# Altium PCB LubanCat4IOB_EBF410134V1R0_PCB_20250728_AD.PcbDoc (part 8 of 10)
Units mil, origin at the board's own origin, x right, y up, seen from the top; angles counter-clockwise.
Board outline 5236.21 x 4055.11 mil, 6 copper layers (TOP, GND02, ART03, PWR04, GND05, BOTTOM), stack 47.2 mil thick; 614 components, 490 nets, 2311 pads, 1916 vias.
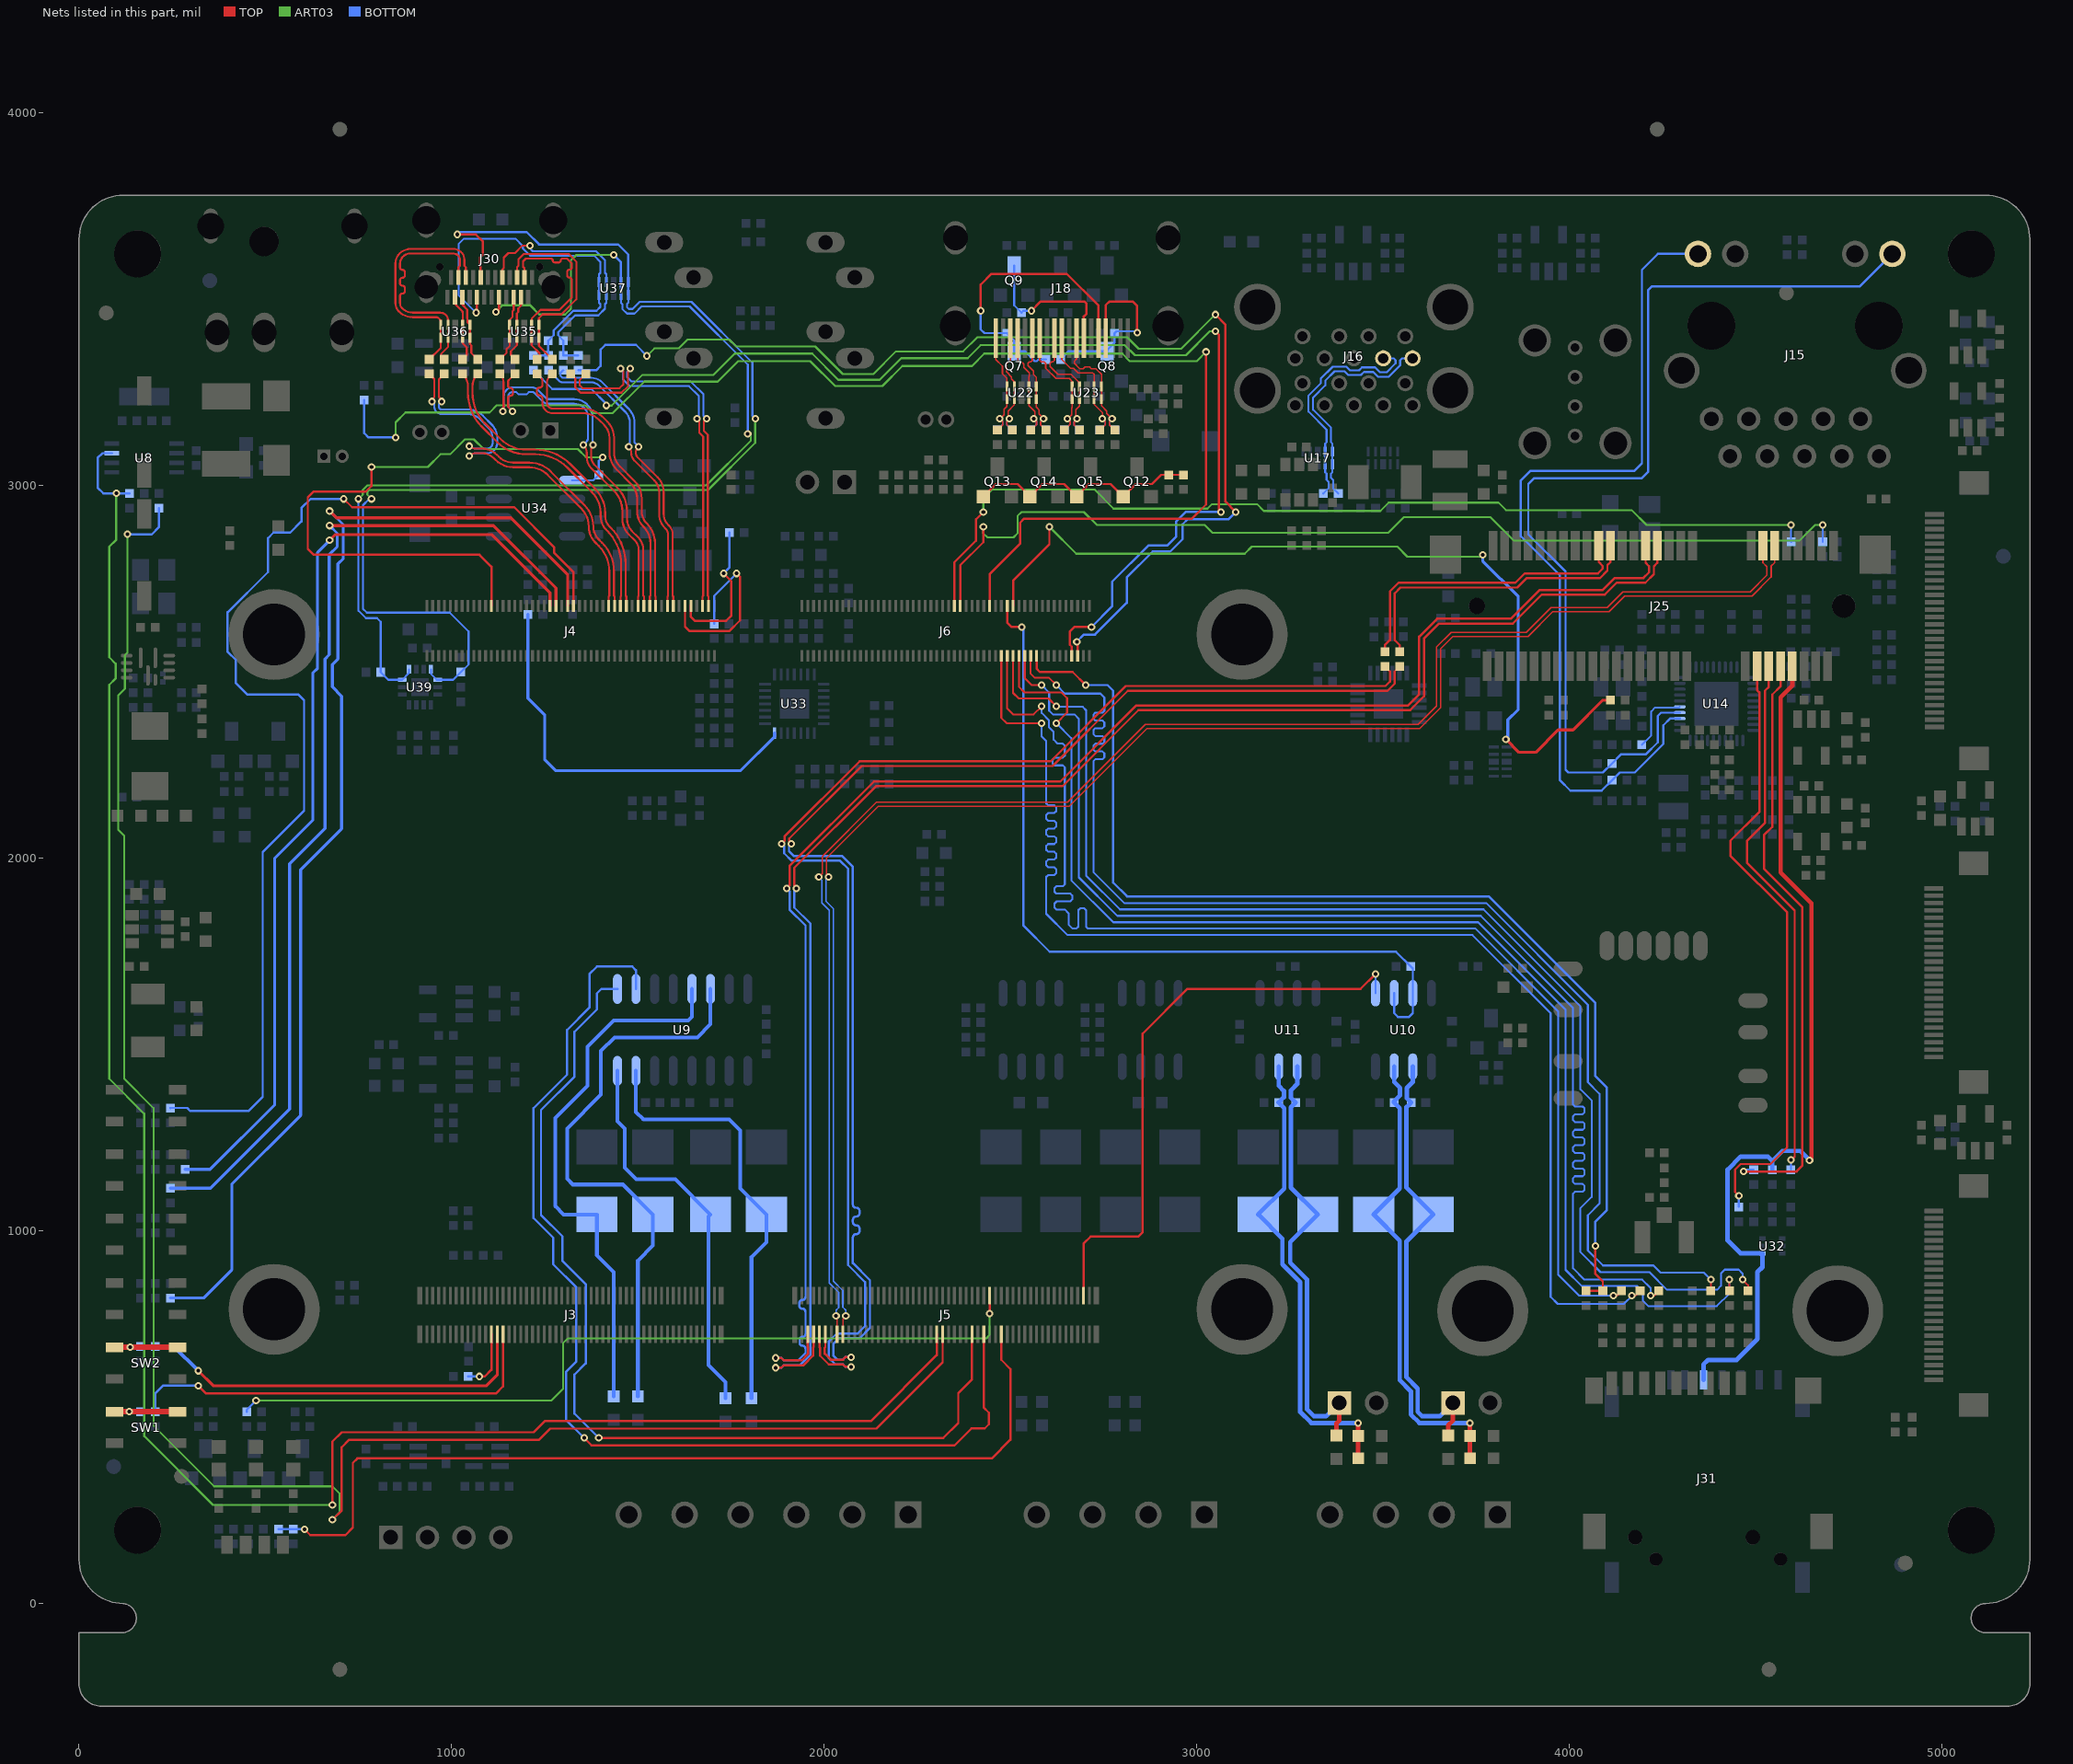
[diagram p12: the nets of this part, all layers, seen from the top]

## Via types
v1: diameter 20, hole 10, TOP to BOTTOM, 1912 vias
v2: diameter 40/50/50/50/50/40 (per signal layer), hole 0, TOP to BOTTOM, 4 vias

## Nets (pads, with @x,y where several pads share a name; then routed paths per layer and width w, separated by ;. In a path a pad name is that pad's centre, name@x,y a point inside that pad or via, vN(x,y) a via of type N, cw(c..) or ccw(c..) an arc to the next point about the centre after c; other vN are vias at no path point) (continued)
OUT2_R: R204.1 U33.14 | length 1085.1
  BOTTOM w8: R204.1@1205,2654.69 1205,2429.37 1250,2384.37 1250,2264.01 1278.64,2235.37 1776,2235.37 1866.85,2326.22 U33.14@1866.85,2335.63
PCIE20_0_CLKN: J5.16 J25.11 | length 4336.7
  TOP w4.2: v1(2011.35,1949.72) 2006.2,1954.87 2006.2,2000.57 2145,2139.37 2657.64,2139.37 2866.24,2347.97 3598.6,2347.97 3655,2404.37 3655,2562.53 3687.64,2595.17 3889,2595.17 3955.6,2661.77 4106.44,2661.77 4148.44,2703.77 4490.4,2703.77 4541.78,2755.15 4541.78,2783.79 4551.32,2793.34 J25.11@4551.32,2838.58 ; J5.16@2050.39,722.26 2050.39,763.87 v1(2058.08,771.56)
  BOTTOM w4.2: v1(2011.35,1949.72) 2010.65,1949.72 2005.1,1944.17 2005.1,1884.34 2024.6,1864.84 2024.6,865.05 2050.07,839.58 2050.07,795.19 2058.08,787.19 v1(2058.08,771.56)
PCIE20_0_CLKP: J5.14 J25.13 | length 4337
  TOP w4.2: v1(1985.35,1949.72) 1995,1959.37 1995,2005.21 2140.36,2150.57 2653,2150.57 2861.6,2359.17 3593.96,2359.17 3643.8,2409.01 3643.8,2567.17 3683,2606.37 3884.36,2606.37 3950.96,2672.97 4101.8,2672.97 4143.8,2714.97 4485.76,2714.97 4530.58,2759.79 4530.58,2782.59 4519.83,2793.34 J25.13@4519.83,2838.58 ; v1(2032.08,771.56) 2034.64,769 J5.14@2034.64,722.26
  BOTTOM w4.2: v1(1985.35,1949.72) 1993.9,1941.17 1993.9,1879.7 2013.4,1860.2 2013.4,860.41 2038.87,834.94 2038.87,793.98 2032.08,787.19 v1(2032.08,771.56)
PCIE20_0_RXN: J5.6 J25.23 | length 4413.3
  TOP w5.9: v1(1869.39,632.82) 1885.17,632.82 1891.72,639.37 1944.77,639.37 1970.23,664.83 1970.23,686.51 1971.65,687.94 J5.6@1971.65,722.26 ; v1(1925,1919.37) 1920,1924.37 1920,1974.37 2139,2193.37 2639.6,2193.37 2843.65,2397.42 3573.05,2397.42 3610,2434.37 3610,2589.37 3650.6,2629.97 3848.6,2629.97 3926,2707.37 4095.37,2707.37 4127.37,2739.37 4204.2,2739.37 4227.06,2762.23 4227.06,2783.69 4236.36,2792.99 J25.23@4236.36,2838.58
  BOTTOM w5.9: v1(1869.39,632.82) 1885.17,632.82 1891.72,639.37 1935,639.37 1962.85,667.22 1962.85,1825.05 1920,1867.9 1920,1914.37 v1(1925,1919.37)
PCIE20_0_RXP: J5.4 J25.25 | length 4410.4
  TOP w5.9: v1(1869.39,658.82) 1885.17,658.82 1891.72,652.27 1939.43,652.27 1957.33,670.17 1957.33,686.51 1955.9,687.94 J5.4@1955.9,722.26 ; v1(1899,1919.37) 1907.1,1927.47 1907.1,1979.71 2133.66,2206.27 2634.26,2206.27 2838.31,2410.32 3567.71,2410.32 3597.1,2439.71 3597.1,2594.71 3645.26,2642.87 3843.26,2642.87 3920.66,2720.27 4090.03,2720.27 4122.03,2752.27 4198.86,2752.27 4214.16,2767.58 4214.16,2783.69 4204.87,2792.99 J25.25@4204.87,2838.58
  BOTTOM w5.9: v1(1869.39,658.82) 1885.17,658.82 1891.72,652.27 1929.65,652.27 1949.95,672.57 1949.95,683.8 ccw(c1941.97,683.8) 1941.97,691.77 cw(c1941.97,699.75) 1934,699.75 1934,707.4 cw(c1941.97,707.4) 1941.97,715.37 ccw(c1941.97,723.35) 1949.95,723.35 1949.95,782.58 ccw(c1941.58,782.58) 1941.58,790.95 cw(c1941.58,799.33) 1933.2,799.33 1933.2,806.18 cw(c1941.58,806.18) 1941.58,814.55 ccw(c1941.58,822.93) 1949.95,822.93 1949.95,1819.7 1907.1,1862.56 1907.1,1911.27 v1(1899,1919.37)
PCIE20_0_TXN: C156.1 J5.10 | length 3710.4
  TOP w5.9: v1(1912.24,2038.68) 1906.41,2044.51 1906.41,2052.86 2100.92,2247.37 2613.24,2247.37 2815.24,2449.37 3512.09,2449.37 3531.45,2468.73 3531.45,2501.14 C156.1@3545,2514.69 ; J5.10@2003.15,722.26 2003.15,687.94 2001.72,686.51 2001.72,670.27 2017.62,654.37 2050.33,654.37 2056.88,660.92 v1(2072.66,660.92)
  BOTTOM w5.9: v1(1912.24,2038.68) 1905.69,2032.13 1905.69,2018.68 1918,2006.37 2048,2006.37 2077,1977.37 2077,1071.03 ccw(c2086,1071.03) 2086,1062.03 cw(c2086,1053.03) 2095,1053.03 2095,1047.43 cw(c2086,1047.43) 2086,1038.43 ccw(c2086,1029.43) 2077,1029.43 2077,1023.83 ccw(c2086,1023.83) 2086,1014.83 cw(c2086,1005.83) 2095,1005.83 2095,1000.23 cw(c2086,1000.23) 2086,991.23 ccw(c2086,982.23) 2077,982.23 2077,913.61 2123,867.61 2123,739.37 2095.1,711.47 2038.8,711.47 2025,697.67 2025,664.8 2035.43,654.37 2050.33,654.37 2056.88,660.92 v1(2072.66,660.92)
PCIE20_0_TXP: C157.1 J5.8 | length 3712.6
  TOP w5.9: v1(1886.24,2038.68) 1893.29,2045.73 1893.29,2046.53 1893.51,2046.76 1893.51,2058.2 2095.58,2260.27 2607.9,2260.27 2809.9,2462.27 3506.75,2462.27 3518.55,2474.07 3518.55,2501.14 C157.1@3505,2514.69 ; J5.8@1987.4,722.26 1987.4,687.94 1988.82,686.51 1988.82,664.93 2012.28,641.47 2050.33,641.47 2056.88,634.92 v1(2072.66,634.92)
  BOTTOM w5.9: v1(1886.24,2038.68) 1892.79,2032.13 1892.79,2013.34 1912.66,1993.47 2042.66,1993.47 2064.1,1972.03 2064.1,908.27 2110.1,862.27 2110.1,744.71 2089.76,724.37 2033.46,724.37 2012.1,703.01 2012.1,659.46 2030.09,641.47 2050.33,641.47 2056.88,634.92 v1(2072.66,634.92)
PCIE20X1_2_CLKREQN_M0: J6.54 R179.1 | length 2611.2
  TOP w6: J6.54@2349.6,2677.37 2349.6,2794.35 2407.62,2852.37 2407.62,2909.68 v1(2427.31,2929.37)
  ART03 w5.5: v1(2427.31,2929.37) 2427.31,2966.68 2450,2989.37 2726,2989.37 2777,2938.37 3029,2938.37 3041,2950.37 3162,2950.37 3180,2932.37 3493,2932.37 3515,2954.37 3810,2954.37 3830,2934.37 4167.2,2934.37 4207.2,2894.37 v1(4595,2894.37)
  BOTTOM w6: v1(4595,2894.37) 4595,2849.69 R179.1@4595.32,2849.37
PCIE20X1_2_PERSTN_M0: J6.74 R181.2 | length 2367.2
  TOP w6: J6.74@2507.08,2677.37 2507.08,2745.25 2604.47,2842.64 v1(2604.47,2889.37)
  TOP w8: v1(3830,2319.37) 3865,2284.37 3910,2284.37 3970,2344.37 4010,2344.37 4090,2424.37 R181.2@4110.32,2424.37
  ART03 w5.5: v1(2604.47,2889.37) 2676.47,2817.37 3129,2817.37 3148,2836.37 3538.4,2836.37 3565.2,2809.57 3762.81,2809.57 v1(3767.61,2814.37)
  BOTTOM w8: v1(3767.61,2814.37) 3767.61,2797.99 3863,2702.6 3863,2399.33 3835,2371.33 3835,2324.37 v1(3830,2319.37)
PCIE20X1_2_WAKEN_M0: J6.56 R178.1 | length 2697
  TOP w6: J6.56@2365.35,2677.37 2365.35,2786.41 2427.31,2848.37 v1(2427.31,2889.37)
  ART03 w5.5: v1(2427.31,2889.37) 2427.31,2872 2438.31,2861 2508,2861 2519,2872 2519,2918.37 2530,2929.37 2697,2929.37 2732,2894.37 3021,2894.37 3042,2873.37 3514,2873.37 3556,2915.37 3788,2915.37 3850.8,2852.57 4618.2,2852.57 4660,2894.37 v1(4680.32,2894.37)
  BOTTOM w6: R178.1@4680.32,2849.37 v1(4680.32,2894.37)
PE_TXN: C156.2 J25.31 | length 828.7
  TOP w5.9: C156.2@3545,2554.05 3545,2572.07 3531.45,2585.62 3531.45,2710.82 3547.1,2726.47 3860.34,2726.47 3885.34,2751.47 4082.1,2751.47 4102.52,2771.89 4102.52,2786.89 4110.38,2794.75 J25.31@4110.38,2838.58
PE_TXP: C157.2 J25.33 | length 829.9
  TOP w5.9: C157.2@3505,2554.05 3505,2572.07 3518.55,2585.62 3518.55,2716.16 3541.76,2739.37 3855,2739.37 3880,2764.37 4076.76,2764.37 4089.62,2777.23 4089.62,2784.75 4078.88,2795.49 J25.33@4078.88,2838.58
PHY1_CLKOUT125: R97.2 U14.35 | length 182
  BOTTOM w5.2: R97.2@4194.68,2304.37 4220,2329.69 4220,2394.16 4230.48,2404.64 4294.71,2404.64 U14.35@4296.57,2406.5
PHY1_LED1: J15.14 R103.1 U14.33 | length 2322.3
  BOTTOM w6: U14.33@4296.57,2375 4270.63,2375 4252.5,2356.87 4252.5,2306.87 4175.8,2230.17 4135.48,2230.17 R103.1@4114.68,2209.37 4086.68,2181.37 4003,2181.37 3975,2209.37 3975,2759.37 3870,2864.37 3870,3014.37 3895,3039.37 4174,3039.37 4195,3060.37 4195,3579.37 4237.68,3622.05 J15.14@4345.46,3622.05
PHY1_LED2: J15.11 R102.1 U14.34 | length 2744.8
  BOTTOM w6: U14.34@4296.57,2390.75 4246.38,2390.75 4237.6,2381.97 4237.6,2310.96 4206.01,2279.37 4139.68,2279.37 R102.1@4114.68,2254.37 4090.48,2230.17 3997.33,2230.17 3990,2237.5 3990,2769.37 3890,2869.37 3890,3004.37 3905,3019.37 4194,3019.37 4212,3037.37 4212,3525.37 4221,3534.37 4779.44,3534.37 J15.11@4867.12,3622.05
PWM7_IR_M0: C46.1 J5.70 R45.1 | length 2472.5
  TOP w6: v1(605,199.05) 620.68,183.37 715,183.37 735,203.37 735,377.37 747,389.37 2450,389.37 2500,439.37 2500,629.37 2475.59,653.78 J5.70@2475.59,722.26
  BOTTOM w6: R45.1@535,199.05 C46.1@575,199.05 v1(605,199.05)
PWRON_EN: J3.24 R238.2 | length 164.6
  TOP w6: v1(1075,609.37) 1089,609.37 1106.78,627.15 J3.24@1106.78,722.26
  BOTTOM w6: R238.2@1044.68,609.37 v1(1075,609.37)
PWRON_KEY: C39.1 J3.28 SW1.3 SW1.4 Z1.2 | length 1387.8
  TOP w6: v1(320,584.37) 341,563.37 1119,563.37 1138.28,582.65 J3.28@1138.28,722.26
  TOP w15: SW1.3@95.35,514.76 v1(135,514.76) SW1.4@264.65,514.76
  BOTTOM w6: v1(135,514.76) 135.71,514.05 Z1.2@165,514.05 C39.1@205,514.05 205,564.37 225,584.37 v1(320,584.37)
RESET_KEY: C41.1 J3.26 SW2.3 SW2.4 Z2.2 | length 1320
  TOP w8: v1(320,624.37) 360,584.37 1094,584.37 1122.53,612.9 J3.26@1122.53,722.26
  TOP w15: SW2.3@95.35,687.48 v1(137.52,687.48) SW2.4@264.65,687.48
  BOTTOM w10: v1(137.52,687.48) 139.72,689.68 Z2.2@165,689.68 C41.1@205,689.68 254.69,689.68 v1(320,624.37)
RS485_1_A: D20.2 J11.1 R62.2 R67.1 U10.6 | length 1222.4
  TOP w12: R67.1@3675,450.87 3675,478.02 3687.67,490.69 J11.1@3687.67,538.19
  BOTTOM w12: U10.6@3580,1440.94 3580,1399.37 3563.65,1383.02 3563.65,1356.04 R62.2@3575.32,1344.37 3563,1332.05 3563,1115.82 D20.2@3635,1043.82 3563,971.82 3563,606.83 3593,576.83 3593,514.37 3605,502.37 3651.85,502.37 J11.1@3687.67,538.19
RS485_1_B: D18.2 R63.1 R64.1 R66.1 U10.7 | length 1286.7
  TOP w12: R66.1@3733.5,389.37 R63.1@3733.5,449.37 v1(3733.5,484.37)
  BOTTOM w12: U10.7@3530,1440.94 3530,1399.37 3545.65,1383.72 3545.65,1363.54 3529.68,1347.58 R64.1@3529.68,1344.37 3545,1329.05 3545,1113.82 D18.2@3475,1043.82 3545,973.82 3545,599.37 3575,569.37 3575,506.91 3597.54,484.37 v1(3733.5,484.37)
RS485_2_A: D22.2 J13.1 R69.1 R70.2 U11.6 | length 1216
  TOP w12: R69.1@3375,450.87 3375,483.02 3382.67,490.69 J13.1@3382.67,538.19
  BOTTOM w12: U11.6@3270,1440.94 3270,1394.37 3253,1377.37 3253,1356.69 R70.2@3265.32,1344.37 3252.88,1331.93 3252.88,1115.94 D22.2@3325,1043.82 3251,969.82 3251,914.57 3295.6,869.97 3295.6,521.57 3314.8,502.37 3346.85,502.37 J13.1@3382.67,538.19
RS485_2_B: D21.2 R68.1 R71.1 R72.1 U11.7 | length 1283.7
  TOP w12: R68.1@3433.5,389.37 R71.1@3433.5,449.37 v1(3433.5,484.37)
  BOTTOM w12: U11.7@3220,1440.94 3220,1389.37 3233.85,1375.52 3233.85,1358.54 R72.1@3219.68,1344.37 3234.88,1329.17 3234.88,1113.7 D21.2@3165,1043.82 3165.32,1043.82 3230,979.1 3230,910.11 3277.6,862.51 3277.6,514.11 3307.34,484.37 v1(3433.5,484.37)
RTC_32K_IN: J5.50 R48.2 | length 5227.3
  TOP w6: v1(680,224.37) 705,249.37 705,419.37 725,439.37 1235,439.37 1265,469.37 2140,469.37 2318.11,647.48 J5.50@2318.11,722.26
  ART03 w5.5: v1(130,2869.37) 130,2552 123,2545 123,2455.09 105,2437.09 105,2076.37 121,2060.37 121,1408.37 200,1329.37 200,477 362.63,314.37 680,314.37 700,294.37 700,244.37 v1(680,224.37)
  BOTTOM w6: v1(130,2869.37) 195,2869.37 215,2889.37 R48.2@215,2939.69
RTC_INT: J5.48 R46.2 U8.3 | length 5331.7
  TOP w6: v1(680,264.37) 680,434.37 705,459.37 1220,459.37 1250,489.37 2125,489.37 2302.36,666.73 J5.48@2302.36,722.26
  ART03 w6: v1(100,2979.37) 100,2855.37 81,2836.37 81,2539.37 98,2522.37 98,2482.37 81,2465.37 81,1408.37 175,1314.37 175,449.37 360,264.37 v1(680,264.37)
  BOTTOM w6: U8.3@88.39,3087.16 62.8,3087.16 50,3074.37 50,2994.37 65,2979.37 v1(100,2979.37) 100.32,2979.05 R46.2@135,2979.05
RXD1_232: D8.2 R51.1 U9.13 | length 1480
  BOTTOM w10: R51.1@1435,555.87 1435,889.37 1390,934.37 D8.2@1390,1043.82 1300.55,1043.82 1278,1066.37 1278,1302.37 1365,1389.37 1365,1494.37 1435,1564.37 1635,1564.37 1645.2,1574.57 U9.13@1645.2,1649.17
RXD2_232: D7.2 R49.1 U9.8 | length 1064.3
  BOTTOM w10: U9.8@1445.2,1429.57 1445.2,1294.17 1465,1274.37 1465,1169.37 1496,1138.37 1600.45,1138.37 D7.2@1695,1043.82 1689.75,1038.57 1689.75,639.62 1735,594.37 R49.1@1735,550.87
SARADC_BOOT: J4.52 R239.2 | length 3088.1
  TOP w6: v1(710.63,2964.37) 733,2942 1168,2942 1275,2835 1275,2820 1327.25,2767.75 J4.52@1327.25,2677.37
  BOTTOM w6: R239.2@245,1329.68 245.32,1330 290,1330 298.49,1321.51 454.51,1321.51 493,1360 493,2017 604,2128 604,2424 589,2439 452,2439 421,2470 421,2532 399,2554 399,2660 507,2768 507,2859 522,2874 567,2874 597,2904 597,2940 621.37,2964.37 v1(710.63,2964.37)
SARADC_IN1/REC: J4.50 R28.2 | length 3186.8
  TOP w8: v1(672.63,2932.11) 691,2913.74 1159.63,2913.74 1311.5,2761.87 J4.50@1311.5,2677.37
  BOTTOM w8: R28.2@245,819.69 334.69,819.69 410,895 410,1125 595,1310 595,1969.37 705,2079.37 705,2435 680,2460 680,2520 695,2535 695,2790 709,2804 709,2895.74 v1(672.63,2932.11)
SARADC_IN4: J4.46 R31.2 | length 2759.8
  TOP w8: v1(672.63,2892.74) 1112.63,2892.74 1280.01,2725.36 J4.46@1280.01,2677.37
  BOTTOM w8: R31.2@245,1114.68 352.68,1114.68 565,1327 565,1985 660,2080 660,2535 671.31,2546.31 671.31,2814.68 693,2836.37 693,2872.37 v1(672.63,2892.74)
SARADC_IN5: J4.44 R33.2 | length 2586.1
  TOP w8: v1(672.63,2853.37) 688,2868.74 1107.63,2868.74 1264.26,2712.11 J4.44@1264.26,2677.37
  BOTTOM w8: R33.2@284.68,1165 352,1165 525,1338 525,2000 627.51,2102.51 627.51,2497.51 640,2510 640,2820.74 v1(672.63,2853.37)
SBU_1: C201.1 J30.A8 R226.1 R229.1 U37.1 U37.10 | length 1051.1
  TOP w5.3: v1(1065.63,3464.43) 1067.71,3466.52 J30.A8@1067.71,3506.29
  BOTTOM w5.3: v1(1065.63,3464.43) 1018.65,3511.41 1018.65,3648.02 1033.6,3662.97 1171.4,3662.97 1191.35,3643.02 1191.35,3636.64 1210.88,3617.12 1382.25,3617.12 1399.33,3600.05 1399.33,3571.37 1395.63,3567.68 U37.1@1395.63,3546.59 U37.10@1395.63,3512.15 1395.63,3491.06 1399.33,3487.37 1399.33,3479.87 1388.82,3469.37 1326.36,3469.37 1273.85,3416.86 1273.85,3403.54 R229.1@1259.68,3389.37
  BOTTOM w6: R226.1@1220,3349.05 C201.1@1260,3349.05 1259.68,3349.37 R229.1@1259.68,3389.37
SBU_2: C202.1 J30.B8 R227.1 R228.1 U37.2 U37.9 | length 753.4
  TOP w5.3: J30.B8@1136.61,3559.05 1136.61,3580.98 1140,3584.37 1140,3611.86 1152.51,3624.37 1170,3624.37 1190,3644.37 v1(1210,3644.37)
  BOTTOM w5.3: v1(1210,3644.37) 1210,3637.37 1217.95,3629.42 1387.35,3629.42 1411.62,3605.14 1411.62,3571.37 1415.32,3567.68 U37.2@1415.32,3546.59 U37.9@1415.32,3512.15 1415.32,3491.06 1411.62,3487.37 1411.62,3474.78 1393.92,3457.07 1331.45,3457.07 1286.15,3411.77 1286.15,3403.54 R228.1@1300.32,3389.37
  BOTTOM w6: R228.1@1300.32,3389.37 1300.32,3349.37 C202.1@1300,3349.05 R227.1@1340,3349.05
SDMMC_CLK: J6.77 R57.1 | length 3451.6
  TOP w5.2: J6.77@2538.57,2543.51 2538.57,2483.43 2557.28,2464.72 v1(2584,2464.72) ; v1(4218,826) 4226.95,826 R57.1@4240,839.05
  BOTTOM w5.2: v1(2584,2464.72) 2604,2444.72 2604,2396 2614,2386 2672,2386 2683.6,2374.4 2683.6,1948.77 2786.8,1845.57 3762.45,1845.57 4010,1598.02 4010,1338.98 4015.2,1333.78 4035.8,1333.78 4041,1328.58 4041,1318.18 4035.8,1312.98 4015.2,1312.98 4010,1307.78 4010,1297.38 4015.2,1292.18 4035.8,1292.18 4041,1286.98 4041,1276.58 4035.8,1271.38 4015.2,1271.38 4010,1266.18 4010,1255.78 4015.2,1250.58 4035.8,1250.58 4041,1245.38 4041,1234.98 4035.8,1229.78 4015.2,1229.78 4010,1224.58 4010,1214.18 4015.2,1208.98 4035.8,1208.98 4041,1203.78 4041,1193.38 4035.8,1188.18 4015.2,1188.18 4010,1182.98 4010,1172.58 4015.2,1167.38 4035.8,1167.38 4041,1162.18 4041,1151.78 4035.8,1146.58 4015.2,1146.58 4010,1141.38 4010,1130.98 4015.2,1125.78 4035.8,1125.78 4041,1120.58 4041,1110.18 4035.8,1104.98 4015.2,1104.98 4010,1099.78 4010,899.7 4040.7,869 4196,869 4218,847 v1(4218,826)
SDMMC_CMD: J6.79 R55.1 | length 3456.7
  TOP w5.2: J6.79@2554.32,2543.51 2554.32,2495.4 2564.72,2485 2603.09,2485 v1(2623.37,2464.72) ; R55.1@4380,839.05 v1(4380,869.37)
  BOTTOM w5.2: v1(2623.37,2464.72) 2646.09,2442 2741.6,2442 2752,2431.6 2752,2395.75 2746.8,2390.55 2727.8,2390.55 2722.6,2385.35 2722.6,2374.95 2727.8,2369.75 2746.8,2369.75 2752,2364.55 2752,2354.15 2746.8,2348.95 2727.8,2348.95 2722.6,2343.75 2722.6,2333.35 2727.8,2328.15 2746.8,2328.15 2752,2322.95 2752,2312.55 2746.8,2307.35 2727.8,2307.35 2722.6,2302.15 2722.6,2291.75 2727.8,2286.55 2746.8,2286.55 2752,2281.35 2752,2270.95 2746.8,2265.75 2727.8,2265.75 2722.6,2260.55 2722.6,1962.88 2805.51,1879.97 3776.7,1879.97 4050,1606.67 4050,1399 4081,1368 4081,1073 4050,1042 4050,947.35 4090.34,907 4226,907 4245,888 4361.37,888 v1(4380,869.37)
SDMMC_D0: J6.69 R58.1 | length 3494.6
  TOP w5.2: J6.69@2475.58,2543.51 2475.58,2376.95 2490.17,2362.37 v1(2584,2362.37) ; v1(4168,826) 4176.95,826 R58.1@4190,839.05
  BOTTOM w5.2: v1(2584,2362.37) 2584,2326.37 2596,2314.37 2596,2147.37 2601.2,2142.17 2617.8,2142.17 2623,2136.97 2623,2126.57 2617.8,2121.37 2601.2,2121.37 2596,2116.17 2596,2105.77 2601.2,2100.57 2617.8,2100.57 2623,2095.37 2623,2084.97 2617.8,2079.77 2601.2,2079.77 2596,2074.57 2596,2064.17 2601.2,2058.97 2617.8,2058.97 2623,2053.77 2623,2043.37 2617.8,2038.17 2601.2,2038.17 2596,2032.97 2596,2022.57 2601.2,2017.37 2617.8,2017.37 2623,2012.17 2623,2001.77 2617.8,1996.57 2601.2,1996.57 2596,1991.37 2596,1980.97 2601.2,1975.77 2617.8,1975.77 2623,1970.57 2623,1960.17 2617.8,1954.97 2601.2,1954.97 2596,1949.77 2596,1851 2653.03,1793.97 3740.4,1793.97 3950,1584.37 3950,823 3969,804 4146,804 v1(4168,826)
SDMMC_D1: J6.71 R59.1 | length 3470
  TOP w5.2: J6.71@2491.33,2543.51 2491.33,2401.67 2507,2386 2562.26,2386 v1(2584,2407.74) ; v1(4118,826) 4126.95,826 R59.1@4140,839.05
  BOTTOM w5.2: v1(2584,2407.74) 2584,2390 2603.39,2370.61 2603.39,2351.61 2616,2339 2616,2318.4 2626.4,2308 2640,2308 2646,2302 2646,2275.24 2640.8,2270.04 2618.4,2270.04 2613.2,2264.84 2613.2,2254.44 2618.4,2249.24 2640.8,2249.24 2646,2244.04 2646,1930.21 2640.8,1925.01 2623.2,1925.01 2618,1919.81 2618,1910.41 2623.2,1905.21 2660.8,1905.21 2666,1900.01 2666,1889.61 2660.8,1884.41 2624.2,1884.41 2618,1878.21 2618,1867.81 2623.2,1862.61 2645.6,1862.61 2656,1852.21 2656,1822 2666.83,1811.17 2677.03,1811.17 2682.23,1816.37 2682.23,1860.8 2687.43,1866 2697.83,1866 2703.03,1860.8 2703.03,1816.37 2708.23,1811.17 3748.2,1811.17 3970,1589.37 3970,883 4027,826 v1(4118,826)
SDMMC_D2: J6.73 R53.1 | length 3490.9
  TOP w5.2: J6.73@2507.08,2543.51 2507.08,2443.92 2522,2429 2602.11,2429 v1(2623.37,2407.74) ; v1(4465,869.37) 4480,854.37 R53.1@4480,839.05
  BOTTOM w5.2: v1(2623.37,2407.74) 2624.74,2406.37 2694,2406.37 2703.4,2396.97 2703.4,1953.3 2793.93,1862.77 3769.57,1862.77 4030,1602.34 4030,1380 4060,1350 4060,1091 4030,1061 4030,943.02 4084.02,889 4215,889 4262,842 4396.6,842 4407,852.4 4407,885.6 4417.4,896 4454.6,896 4465,885.6 v1(4465,869.37)
SDMMC_D3: J6.75 R54.1 | length 3487.9
  TOP w5.2: J6.75@2522.83,2543.51 2522.83,2460.17 2538,2445 2637,2445 2652,2430 2652,2391 v1(2623.37,2362.37) ; R54.1@4430,839.05 v1(4430,869.37)
  BOTTOM w5.2: v1(2623.37,2362.37) 2663.4,2322.34 2663.4,1940.97 2776,1828.37 3755.32,1828.37 3990,1593.69 3990,895.37 4033.57,851.8 4183,851.8 4197,837.8 4197,813 4212,798 4396,798 4430,832 v1(4430,869.37)
SDMMC_DET: J6.81 R60.1 R61.2 | length 3059.4
  TOP w6: J6.81@2570.07,2543.51 2570.07,2508.93 2579,2500 2666.83,2500 v1(2702.11,2464.72) ; R61.2@4045,839.05 R60.1@4090,839.05 4090,864.37 4070,884.37 v1(4070,959.37)
  BOTTOM w6: v1(2702.11,2464.72) 2760.65,2464.72 2776,2449.37 2776,1934.37 2812.8,1897.57 3783.99,1897.57 4070,1611.56 4070,1415.37 4101,1384.37 4101,1056 4070,1025 v1(4070,959.37)
SIM_CLK0: J25.12 R171.1 | length 1433.6
  TOP w6: J25.12@4535.58,2515.74 4535.58,2459.95 4525,2449.37 4525,2094.57 4477.5,2047.07 4477.5,1986.87 4605,1859.37 4605,1199.37 4596.48,1190.85 v1(4595,1190.85)
  BOTTOM w5.2: R171.1@4595,1164.05 v1(4595,1190.85)
SIM_DATA0: J25.10 R173.1 | length 1594
  TOP w6: v1(4468.2,1159.37) 4610,1159.37 4625,1174.37 4625,1869.37 4522.5,1971.87 4522.5,2061.87 4545,2084.37 4545,2439.37 4567.07,2461.44 J25.10@4567.07,2515.74
  BOTTOM w5.2: v1(4468.2,1159.37) 4472.88,1164.05 R173.1@4495,1164.05
SIM_RST0: J25.14 R170.1 | length 1658.4
  TOP w6: v1(4455,1094.37) 4445,1104.37 4445,1164.37 4460,1179.37 4540,1179.37 4585,1224.37 4585,1854.37 4432.5,2006.87 4432.5,2046.87 4510,2124.37 4510,2445.37 4504.08,2451.29 J25.14@4504.08,2515.74
  BOTTOM w5.2: R170.1@4455,1064.05 v1(4455,1094.37)
SIM_VDD: J25.8 J31.1 R169.1 U32.1 | length 2407.7
  TOP w12: J25.8@4598.57,2515.74 4598.57,2462.94 4567.43,2431.8 4567.43,1961.94 4650,1879.37 4650,1194.37 v1(4645,1189.37)
  BOTTOM w12: J31.1@4360.23,600.19 4360.23,641.37 4372.23,653.37 4449,653.37 4505,709.37 4505,889.37 4518.43,902.79 U32.1@4518.43,939.68 4459.69,939.68 4425,974.37 4425,1164.37 4460,1199.37 4533,1199.37 4545,1187.37 ; R169.1@4545,1164.05 4545,1187.37 ; v1(4645,1189.37) 4620,1214.37 4572,1214.37 4545,1187.37
SPK_CTRL: J4.24 R214.1 U34.1 | length 1790.3
  TOP w6: v1(785,3050.37) 785,2999.37 770,2984.37 630,2984.37 614,2968.37 614,2830.37 630,2814.37 1075,2814.37 1106.78,2782.59 J4.24@1106.78,2677.37
  ART03 w5.5: v1(785,3050.37) 936,3050.37 970,3084.37 996,3084.37 1036,3124.37 1060,3124.37 1086,3098.37 1338.63,3098.37 1360.63,3076.37 v1(1405,3076.37)
  BOTTOM w6: U34.1@1323.42,3014.37 1380.32,3014.37 R214.1@1395,3029.05 1395,3066.37 v1(1405,3076.37)
SS_TXN: C97.1 J16.8 U17.4 U17.7 | length 633.7
  BOTTOM w5.3: C97.1@3340,2979.05 3353.85,2992.9 3353.85,3010.52 3348.38,3015.99 3348.38,3032.37 3344.68,3036.06 U17.7@3344.68,3057.15 U17.4@3344.68,3091.59 3344.68,3112.68 3348.38,3116.37 3348.38,3150.32 3300,3198.7 3300,3241.76 3332.7,3274.46 3332.7,3287.07 3365,3319.37 3401.42,3319.37 3411.42,3309.37 3435.55,3309.37 3443.64,3317.46 3478.94,3317.46 3492.03,3304.37 3510,3304.37 3533.84,3328.21 3533.84,3336.46 3528.54,3341.76 J16.8@3500.59,3341.76
SS_TXP: C98.1 J16.9 U17.5 U17.6 | length 633.7
  BOTTOM w5.3: C98.1@3380,2979.05 3366.15,2992.9 3366.15,3015.61 3360.68,3021.09 3360.68,3032.37 3364.37,3036.06 U17.6@3364.37,3057.15 U17.5@3364.37,3091.59 3364.37,3112.68 3360.68,3116.37 3360.68,3155.42 3312.3,3203.79 3312.3,3236.67 3345,3269.37 3345,3281.97 3370.1,3307.07 3396.33,3307.07 3406.33,3297.07 3440.65,3297.07 3448.74,3305.16 3473.85,3305.16 3486.94,3292.07 3515.09,3292.07 3546.14,3323.12 3546.14,3336.46 3551.44,3341.76 J16.9@3579.39,3341.76
SSRX_1N: J30.B10 R223.1 U35.5 U35.6 | length 567.7
  TOP w5.3: J30.B10@1175.98,3559.05 1175.98,3586.35 1179.65,3590.02 1179.65,3607.32 1194,3621.67 1314.5,3621.67 1334.9,3601.27 1334.9,3499.87 1294.5,3459.47 1243.87,3459.47 1234.37,3449.97 U35.6@1234.37,3431.59 U35.5@1234.37,3397.15 1234.37,3374.68 R223.1@1270,3339.05
SSRX_1P: J30.B11 R222.1 U35.4 U35.7 | length 552.7
  TOP w5.3: J30.B11@1195.67,3559.05 1195.67,3583.7 1191.95,3587.42 1191.95,3602.22 1199.1,3609.37 1266.53,3609.37 cw(c1266.53,3604.27) 1271.63,3604.27 ccw(c1276.73,3604.27) 1276.73,3599.17 1287.73,3599.17 ccw(c1287.73,3604.27) 1292.83,3604.27 cw(c1297.93,3604.27) 1297.93,3609.37 1309.4,3609.37 1322.6,3596.17 1322.6,3585.87 cw(c1316.4,3585.87) 1316.4,3579.67 ccw(c1316.4,3573.47) 1310.2,3573.47 1310.2,3564.67 ccw(c1316.4,3564.67) 1316.4,3558.47 cw(c1316.4,3552.27) 1322.6,3552.27 1322.6,3504.97 1289.4,3471.77 1238.78,3471.77 1214.96,3447.96 1214.96,3431.88 U35.7@1214.68,3431.59 U35.4@1214.68,3397.15 1214.68,3376.97 1236.41,3355.24 1236.41,3345.46 R222.1@1230,3339.05
SSRX_2N: J30.A10 R225.1 U36.5 U36.6 | length 184.4
  TOP w5.3: J30.A10@1028.74,3506.29 1028.74,3485.82 1041.95,3472.6 1041.95,3469.81 ; 1041.98,3469.78 1041.98,3448.84 1042.27,3448.56 1042.27,3438.62 U36.6@1049.37,3431.59 U36.5@1049.37,3397.15 1049.37,3380 1053,3376.37 1053,3356.05 R225.1@1070,3339.05
SSRX_2P: J30.A11 R224.1 U36.4 U36.7 | length 184.8
  TOP w5.3: J30.A11@1009.05,3506.29 1009.05,3488.11 1029.65,3467.51 1029.65,3464.72 ; 1029.68,3464.69 U36.7@1029.68,3431.59 U36.4@1029.68,3397.15 1029.68,3382.29 1040.7,3371.27 1040.7,3349.75 R224.1@1030,3339.05
SSTX_1N: C198.1 J30.A3 U35.1 U35.10 | length 182.4
  TOP w5.3: C198.1@1130,3339.05 1147,3356.05 1147,3366.04 1155.63,3374.67 U35.1@1155.63,3397.15 U35.10@1155.63,3431.59 1155.63,3445 1163.05,3452.42 1163.05,3467.61 1166.53,3471.09 J30.A3@1166.53,3506.29
SSTX_1P: C197.1 J30.A2 U35.2 U35.9 | length 182.8
  TOP w5.3: C197.1@1170,3339.05 1159.3,3349.75 1159.3,3360.95 1175.32,3376.97 U35.2@1175.32,3397.15 U35.9@1175.32,3431.59 ; U35.9@1175.35,3431.62 1175.35,3462.51 1178.83,3465.99 1178.83,3475.81 1186.22,3483.19 J30.A2@1186.22,3506.29
SSTX_2N: C200.1 J30.B3 U36.1 U36.10 | length 640.4
  TOP w5.3: 860.66,3623.43 ccw(c888.1,3595.99) 849.3,3596 849.3,3489.71 ccw(c880.78,3489.71) 858.52,3467.45 ccw(c895.65,3504.58) 895.65,3452.07 960.11,3452.07 cw(c960.11,3446.77) 963.86,3450.52 970.63,3443.75 U36.10@970.63,3431.59 U36.1@970.63,3397.15 970.63,3369.68 C200.1@940,3339.05 ; 860.69,3623.46 cw(c889.33,3594.81) 889.33,3635.32 1003.77,3635.32 cw(c1003.78,3602.87) 1024.75,3627.63 cw(c1006.93,3606.6) 1034.49,3606.6 1034.49,3590.13 1038.19,3586.44 J30.B3@1038.19,3559.05
SSTX_2P: C199.1 J30.B2 U36.2 U36.9 | length 638.5
  TOP w5.3: 869.36,3614.73 ccw(c888.1,3595.99) 861.6,3595.99 861.6,3585.7 ccw(c868.1,3585.7) 868.1,3579.2 cw(c868.1,3572.7) 874.6,3572.7 874.6,3564.49 cw(c868.1,3564.49) 868.1,3557.99 ccw(c868.1,3551.49) 861.6,3551.49 861.6,3543.3 ccw(c868.1,3543.3) 868.1,3536.8 cw(c868.1,3530.3) 874.6,3530.3 874.6,3522.09 cw(c868.1,3522.09) 868.1,3515.59 ccw(c868.1,3509.09) 861.6,3509.09 861.6,3489.71 ccw(c880.78,3489.71) 867.22,3476.15 ccw(c895.65,3504.58) 895.65,3464.37 969.93,3464.37 cw(c969.93,3443.38) 984.77,3458.22 ; 869.39,3614.76 cw(c889.33,3594.81) 889.33,3623.02 1003.77,3623.02 cw(c1003.78,3602.87) 1016.8,3618.24 cw(c1006.93,3606.6) 1022.19,3606.6 1022.19,3590.13 1018.5,3586.44 J30.B2@1018.5,3559.05 ; C199.1@980,3339.05 972.45,3346.6 972.45,3354.1 990.32,3371.97 U36.2@990.32,3397.15 U36.9@990.32,3431.59 990.32,3444.83 ccw(c971.39,3444.83) 984.78,3458.22
SYS_LED: J5.65 R38.1 | length 2260.4
  TOP w6: v1(2444.09,778.37) J5.65@2444.09,826.59
  ART03 w5.5: v1(475,544.37) 1267.8,544.37 1299,575.57 1299,698.37 1312,711.37 2435.09,711.37 2444.09,720.37 v1(2444.09,778.37)
  BOTTOM w6: R38.1@450.32,514.37 450.32,519.69 v1(475,544.37)
TX_CEC_PORT: D33.2 J18.13 Q9.3 | length 419.7
  TOP w6.16: v1(2556.48,3469.37) 2581.48,3494.37 2697.92,3494.37 2704.08,3488.21 2704.08,3461.47 2696.85,3454.23 J18.13@2696.85,3395.56
  BOTTOM w6: Q9.3@2510,3590.87 2510,3484.05 D33.2@2529.68,3464.37 2534.68,3469.37 v1(2556.48,3469.37)
TX_D0N_PORT: C118.2 J18.9 R136.1 U23.4 U23.7 | length 361.3
  TOP w4.2: J18.9@2618.1,3395.56 2618.1,3336.69 2613.9,3332.49 2610.22,3332.49 2606.02,3328.29 2606.02,3319.77 2627.12,3298.67 2662.69,3298.67 2685.32,3276.04 U23.4@2685.32,3266.59 U23.7@2685.32,3232.15 2685.32,3213.85 2675.32,3203.85 2675.32,3183.05 v1(2679,3179.37) 2671.39,3171.76 2671.39,3162.66 R136.1@2685,3149.05
  BOTTOM w4.2: v1(2679,3179.37) 2670.93,3171.3 2670.93,3163.12 C118.2@2685,3149.05
TX_D0P_PORT: C117.2 J18.7 R134.1 U23.5 U23.6 | length 361.6
  TOP w4.2: J18.7@2578.73,3395.56 2578.73,3336.69 2582.93,3332.49 2590.62,3332.49 2594.82,3328.29 2594.82,3315.13 2622.48,3287.47 2658.05,3287.47 2665.63,3279.89 U23.5@2665.63,3266.59 U23.6@2665.63,3232.15 2665.63,3210 2664.12,3208.49 2664.12,3190.49 v1(2653,3179.37) 2660.19,3172.18 2660.19,3164.24 R134.1@2645,3149.05
  BOTTOM w4.2: C117.2@2645,3149.05 2659.73,3163.78 2659.73,3172.64 v1(2653,3179.37)
TX_D1N_PORT: C115.2 J18.6 R138.1 U22.1 U22.10 | length 319.5
  TOP w4.2: J18.6@2559.05,3395.56 2559.05,3336.69 2554.85,3332.49 2551.22,3332.49 2547.02,3328.29 2547.02,3322.35 2562,3307.37 2562,3298.22 2569.37,3290.84 U22.1@2569.37,3266.59 U22.10@2569.37,3232.15 2569.37,3211 2577,3203.37 2577,3192.37 2587,3182.37 2587,3181.37 v1(2589,3179.37) 2581,3171.37 2581,3163.05 R138.1@2595,3149.05
  BOTTOM w4.2: v1(2589,3179.37) 2581.1,3171.47 2581.1,3162.95 C115.2@2595,3149.05
TX_D1P_PORT: C114.2 J18.4 R137.1 U22.2 U22.9 | length 319.3
  TOP w4.2: J18.4@2519.68,3395.56 2519.68,3336.69 2523.88,3332.49 2529.57,3332.49 2535.82,3326.23 2535.82,3317.71 2550.8,3302.73 2550.8,3293.57 2549.68,3292.45 U22.2@2549.68,3266.59 U22.9@2549.68,3232.15 2549.68,3214.85 2565.8,3198.73 2565.8,3182.17 v1(2563,3179.37) 2569.8,3172.57 2569.8,3163.85 R137.1@2555,3149.05
  BOTTOM w4.2: C114.2@2555,3149.05 2569.9,3163.95 2569.9,3172.47 v1(2563,3179.37)
TX_D2N_PORT: C116.2 J18.3 R141.1 U22.4 U22.7 | length 315.7
  TOP w4.2: J18.3@2499.99,3395.56 2499.99,3337.37 2489.91,3327.29 2489.91,3304.83 2502.97,3291.76 2502.97,3286.4 2510.32,3279.05 U22.4@2510.32,3266.59 U22.7@2510.32,3232.15 2510.32,3216.69 2494,3200.37 2494,3183.8 2497.47,3180.33 v1(2497.47,3179.58) 2490.31,3172.42 2490.31,3163.74 R141.1@2505,3149.05
  BOTTOM w4.2: v1(2497.47,3179.58) 2490.6,3172.71 2490.6,3163.45 C116.2@2505,3149.05
TX_D2P_PORT: C113.2 J18.1 R140.1 U22.5 U22.6 | length 315.4
  TOP w4.2: J18.1@2460.62,3395.56 2460.62,3338.75 2478.71,3320.66 2478.71,3300.19 2490.63,3288.26 U22.5@2490.63,3266.59 U22.6@2490.63,3232.15 2490.63,3212.84 2482.8,3205.01 2482.8,3190.67 v1(2471.47,3179.34) 2479.11,3171.7 2479.11,3163.16 R140.1@2465,3149.05
  BOTTOM w4.2: C113.2@2465,3149.05 2465,3149.71 2479.4,3164.11 2479.4,3171.41 v1(2471.47,3179.34)
TX_D3N_PORT: C120.2 J18.12 R144.1 U23.1 U23.10 | length 367.4
  TOP w4.2: J18.12@2677.16,3395.56 2677.16,3339.53 2671.84,3334.21 2671.84,3328.27 2686.12,3313.99 2695.62,3313.99 2700,3318.37 2712.62,3318.37 2717,3313.99 2729.38,3313.99 2744.37,3299 U23.1@2744.37,3266.59 U23.10@2744.37,3232.15 2744.37,3214.27 2758.2,3200.44 2758.2,3194.17 v1(2773,3179.37) 2765.89,3172.26 2765.89,3163.16 R144.1@2780,3149.05
  BOTTOM w4.2: v1(2773,3179.37) 2765.93,3172.3 2765.93,3163.12 C120.2@2780,3149.05
TX_D3P_PORT: C119.2 J18.10 R143.1 U23.2 U23.9 | length 368.1
  TOP w4.2: J18.10@2637.79,3395.56 2637.79,3338.58 2661.5,3314.87 2669.4,3314.87 2681.48,3302.79 2720.48,3302.79 2724.68,3298.59 U23.2@2724.68,3266.59 U23.9@2724.68,3232.15 2724.68,3218.12 2747,3195.8 v1(2747,3179.37) 2754.69,3171.68 2754.69,3163.74 R143.1@2740,3149.05
  BOTTOM w4.2: C119.2@2740,3149.05 2754.73,3163.78 2754.73,3171.64 v1(2747,3179.37)
TX_ON: Q12.1 Q13.1 Q14.1 Q15.1 R145.2 R146.1 | length 644.9
  TOP w6: Q13.1@2427.5,2970.87 2461,3004.37 2519,3004.37 Q14.1@2552.5,2970.87 2586,3004.37 2644,3004.37 Q15.1@2677.5,2970.87 2711,3004.37 2769,3004.37 Q12.1@2802.5,2970.87 2802.87,2970.87 2836.37,3004.37 2880,3004.37 2904.68,3029.05 R146.1@2925,3029.05 R145.2@2965,3029.05
TX_SCL_PORT: D31.2 J18.15 Q7.3 R128.2 | length 800.5
  TOP w6.16: v1(2420,3469.37) 2420,3539.37 2449.08,3568.45 2650.92,3568.45 2736.22,3483.15 J18.15@2736.22,3395.56
  BOTTOM w6: v1(2420,3469.37) 2420,3419.37 2430,3409.37 D31.2@2490.32,3409.37 2510,3389.69 Q7.3@2510,3360.87 2538.5,3360.87 2565.32,3334.05 2570.6,3334.05 2575.6,3339.05 R128.2@2595,3339.05
TX_SDA_PORT: D30.2 J18.16 Q8.3 R131.2 | length 507.4
  TOP w6.16: J18.16@2755.9,3395.56 2755.9,3484.37 2765.9,3494.37 2827.68,3494.37 2840,3482.05 v1(2840,3411.17)
  BOTTOM w6: R131.2@2635,3339.05 2656.82,3360.87 Q8.3@2760,3360.87 2760,3364.37 2779.68,3384.05 D30.2@2779.68,3409.37 2784.68,3414.37 2836.8,3414.37 v1(2840,3411.17)
TXD1_232: D10.2 R52.1 U9.14 | length 1573.6
  BOTTOM w10: R52.1@1500,555.87 1500,920.49 1540,960.49 D10.2@1540,1043.82 1459.45,1124.37 1325,1124.37 1310,1139.37 1310,1274.37 1401,1365.37 1401,1483 1437.37,1519.37 1659.8,1519.37 1694.8,1554.37 U9.14@1694.8,1649.17
TXD2_232: D9.2 R50.1 U9.7 | length 1175.2
  BOTTOM w10: U9.7@1494.8,1429.57 1494.8,1319.37 1514.8,1299.37 1745,1299.37 1775,1269.37 1775,1113.82 D9.2@1845,1043.82 1845,969.37 1805,929.37 R50.1@1805,550.87
TYPE_C_PWR_EN: J6.66 R236.1 | length 3747.5
  TOP w6: J6.66@2444.09,2677.37 2444.09,2762.46 2525.73,2844.1 2525.73,2900.1 2537,2911.37 2987,2911.37 3025,2949.37 v1(3025,3359.37)
  ART03 w5.5: v1(850,3129.37) 850,3170 876.37,3196.37 1102,3196.37 1121.05,3215.42 1358.95,3215.42 1380,3194.37 1432,3194.37 1517,3279.37 1714,3279.37 1769,3334.37 1962.63,3334.37 2029.63,3267.37 2156.13,3267.37 2210.13,3321.37 2397,3321.37 2430,3354.37 2800,3354.37 2820,3334.37 3000,3334.37 v1(3025,3359.37)
  BOTTOM w6: R236.1@765.32,3229.37 765.32,3141.37 777.32,3129.37 v1(850,3129.37)
TYPEC0_OTG_DM: J4.98 R221.2 | length 1075.1
  TOP w5.3: R221.2@1320,3299.69 1331.85,3287.84 1331.85,3263.88 1346.36,3249.37 1455.85,3249.37 1473.65,3267.18 1473.65,3308.02 v1(1480,3314.37) ; v1(1684.15,3179.37) 1677.3,3172.52 1677.3,3147.07 1687.73,3136.64 1687.73,2704.52 1689.46,2702.8 J4.98@1689.46,2677.37
  BOTTOM w5.3: v1(1480,3314.37) 1471.7,3306.07 1471.7,3291.07 1483.4,3279.37 1642.3,3279.37 1676.3,3245.37 1676.3,3187.22 v1(1684.15,3179.37)
TYPEC0_OTG_DP: J4.96 R220.2 | length 1034.4
  TOP w5.3: R220.2@1360,3299.69 1344.15,3283.84 1344.15,3268.97 1351.45,3261.67 1450.75,3261.67 1461.35,3272.27 1461.35,3307.02 v1(1454,3314.37) ; v1(1658.15,3179.37) 1665,3172.52 1665,3141.97 1675.43,3131.54 1675.43,2704.52 1673.71,2702.8 J4.96@1673.71,2677.37
  BOTTOM w5.3: v1(1454,3314.37) 1459.4,3308.97 1459.4,3285.98 1478.31,3267.07 1637.2,3267.07 1664,3240.28 1664,3185.6 1658.15,3179.75 v1(1658.15,3179.37)
TYPEC0_OTG_VBUSDET: J4.92 R233.2 | length 386.5
  TOP w6: J4.92@1642.21,2677.37 1642.21,2647.77 1652.61,2637.37 1737,2637.37 1751,2651.37 1751,2743.37 v1(1730,2764.37)
  BOTTOM w6: v1(1730,2764.37) 1745.32,2779.69 R233.2@1745.32,2874.37
TYPEC0_SBU1/DP0_AUXP: C201.2 J4.84 | length 813
  TOP w5.3: v1(1475.33,3104.7) 1475.52,3104.5 cw(c1459.44,3088.43) 1482.18,3088.43 ccw(c1517.86,3088.16) 1482.18,3088.16 ccw(c1512.02,3088.16) 1490.91,3067.06 1544.42,3013.55 cw(c1514.17,2983.29) 1556.96,2983.29 1556.96,2924.37 ccw(c1610.92,2924.37) 1572.76,2886.21 1574.3,2884.67 cw(c1558.27,2868.64) 1580.94,2868.64 1580.94,2704.52 1579.22,2702.8 J4.84@1579.22,2677.37
  BOTTOM w5.3: C201.2@1260,3309.69 1287.59,3282.1 ccw(c1300.04,3294.54) 1300.04,3276.94 1376.26,3276.94 cw(c1376.26,3249.97) 1395.33,3269.04 1465.95,3198.42 cw(c1435.3,3167.76) 1478.65,3167.76 1478.65,3108.02 v1(1475.33,3104.7)
TYPEC0_SBU1_DC: J6.93 R226.2 | length 3194
  TOP w6: J6.93@2664.56,2543.51 2664.56,2568.05 2659.11,2573.5 2659.11,2608.48 2671.37,2620.74 v1(2717.48,2620.74) ; v1(3050,3414.37) 3060,3404.37 3060,2934.37 v1(3065,2929.37)
  ART03 w5.5: v1(1415.69,3215.06) 1429.69,3215.06 1512,3297.37 1703,3297.37 1760,3354.37 1968,3354.37 2038,3284.37 2149,3284.37 2206.7,3342.07 2385.09,3342.07 2420.09,3377.07 2807.3,3377.07 2834,3350.37 2971,3350.37 3035,3414.37 v1(3050,3414.37)
  BOTTOM w6: R226.2@1220,3309.69 1270.4,3259.29 1375.08,3259.29 1415,3219.37 1415,3215.75 v1(1415.69,3215.06) ; v1(2717.48,2620.74) 2772.74,2676 2772.74,2742.11 2870,2839.37 2921,2839.37 2945,2863.37 2945,2904.37 2970,2929.37 v1(3065,2929.37)
TYPEC0_SBU2/DP0_AUXN: C202.2 J4.86 | length 811
  TOP w5.3: v1(1501.33,3104.7) ccw(c1517.86,3088.16) 1494.48,3088.47 1494.48,3088.37 ccw(c1517.86,3088.05) 1494.48,3088.16 ccw(c1512.02,3088.16) 1499.61,3075.76 1553.12,3022.25 cw(c1514.17,2983.29) 1569.26,2983.3 1569.26,2924.37 ccw(c1610.92,2924.37) 1581.46,2894.91 1583,2893.37 cw(c1558.27,2868.64) 1593.24,2868.64 1593.24,2704.52 1594.97,2702.8 J4.86@1594.97,2677.37
  BOTTOM w5.3: C202.2@1300,3309.69 1299.47,3309.69 1291.82,3302.04 1291.82,3295.26 1296.29,3290.79 ccw(c1300.04,3294.54) 1300.04,3289.24 1376.26,3289.24 cw(c1376.26,3249.97) 1404.03,3277.74 1474.65,3207.11 cw(c1435.3,3167.76) 1490.95,3167.76 1490.95,3115.72 1501.33,3105.35 v1(1501.33,3104.7)
TYPEC0_SBU2_DC: J6.95 R227.2 | length 3150.6
  TOP w6: v1(2678.11,2581.37) 2680.31,2579.17 J6.95@2680.31,2543.51 ; v1(3050,3459.37) 3077.3,3432.07 3077.3,2957.07 v1(3105,2929.37)
  ART03 w5.5: v1(1524.37,3348.37) 1544.37,3368.37 1609,3368.37 1633,3392.37 1745,3392.37 1764,3373.37 1976,3373.37 2050,3299.37 2132,3299.37 2193,3360.37 2373,3360.37 2411,3398.37 2813,3398.37 2844,3367.37 2958,3367.37 v1(3050,3459.37)
  BOTTOM w6: R227.2@1340,3309.69 1388,3309.69 1400,3321.69 1400,3365.37 1412.49,3377.86 1494.88,3377.86 v1(1524.37,3348.37) ; v1(2678.11,2581.37) 2697.11,2600.37 2727,2600.37 2812.11,2685.48 2812.11,2753.48 2882,2823.37 2929,2823.37 2962,2856.37 2962,2896.37 2976,2910.37 3086,2910.37 v1(3105,2929.37)
TYPEC0_SSRX1N/DP0_TX0N: J4.80 R223.2 | length 799.6
  TOP w5.3: R223.2@1270,3299.69 1261.7,3291.39 ccw(c1275.09,3277.99) 1256.15,3277.99 1256.15,3222.3 ccw(c1271.78,3222.3) 1271.78,3206.67 1354.16,3206.67 cw(c1354.16,3136.79) 1403.57,3186.2 1418.15,3171.62 cw(c1375.06,3128.53) 1436,3128.53 1436,3089.58 ccw(c1489.63,3089.58) 1451.71,3051.66 1490.88,3012.49 cw(c1444.23,2965.84) 1510.2,2965.84 1510.2,2931.68 ccw(c1557.31,2931.68) 1524,2898.37 cw(c1470.89,2845.26) 1546,2845.26 1546,2704.52 1547.72,2702.8 J4.80@1547.72,2677.37
TYPEC0_SSRX1P/DP0_TX0P: J4.78 R222.2 | length 817.1
  TOP w5.3: R222.2@1230,3299.69 1240.43,3289.26 cw(c1232.16,3281) 1243.85,3281 1243.85,3270.7 cw(c1236.33,3270.7) 1236.33,3263.17 ccw(c1236.33,3255.65) 1228.8,3255.65 1228.8,3249.5 ccw(c1236.33,3249.5) 1236.33,3241.97 cw(c1236.33,3234.45) 1243.85,3234.45 1243.85,3222.3 ccw(c1271.78,3222.3) 1271.78,3194.37 1354.16,3194.37 cw(c1354.15,3136.79) 1394.87,3177.5 1409.45,3162.92 cw(c1375.06,3128.53) 1423.7,3128.53 1423.7,3089.58 ccw(c1489.63,3089.58) 1443.01,3042.96 1482.18,3003.79 cw(c1444.23,2965.84) 1497.9,2965.84 1497.9,2931.68 ccw(c1557.31,2931.68) 1515.3,2889.67 cw(c1470.89,2845.26) 1533.7,2845.26 1533.7,2704.52 1531.97,2702.8 J4.78@1531.97,2677.37
TYPEC0_SSRX2N/DP0_TX2N: J4.70 R225.2 | length 840.8
  TOP w5.3: R225.2@1070,3299.69 ccw(c1103.44,3266.25) 1056.15,3266.25 1056.15,3249.37 ccw(c1173.85,3249.37) 1090.62,3166.14 1131.71,3125.05 ccw(c1200.23,3193.57) 1200.23,3096.67 1225,3096.67 cw(c1225,2963.66) 1319.05,3057.71 1378.7,2998.07 1385.82,2990.95 cw(c1321.63,2926.77) 1412.4,2926.77 1412.4,2917.89 ccw(c1451.32,2917.89) 1423.8,2890.37 1426.57,2887.6 cw(c1328.34,2789.37) 1467.26,2789.37 1467.26,2704.52 1468.98,2702.8 J4.70@1468.98,2677.37
TYPEC0_SSRX2P/DP0_TX2P: J4.68 R224.2 | length 840.8
  TOP w5.3: R224.2@1030,3299.69 cw(c996.56,3266.25) 1043.85,3266.25 1043.85,3249.37 ccw(c1173.85,3249.37) 1081.93,3157.44 1123.02,3116.35 ccw(c1200.23,3193.57) 1200.23,3084.37 1225,3084.37 cw(c1225,2963.66) 1310.36,3049.02 1370,2989.37 1377.12,2982.25 cw(c1321.63,2926.77) 1400.1,2926.77 1400.1,2917.89 ccw(c1451.32,2917.89) 1415.1,2881.67 1417.87,2878.9 cw(c1328.34,2789.37) 1454.96,2789.37 1454.96,2704.52 1453.23,2702.8 J4.68@1453.23,2677.37
TYPEC0_SSTX1N/DP0_TX1N: C198.2 J4.76 | length 992.9
  TOP w5.3: C198.2@1130,3299.69 cw(c1107.66,3277.35) 1139.25,3277.35 1139.25,3203.12 cw(c1133.95,3203.12) 1139.22,3202.51 v1(1137.7,3199.37) ; v1(1380,3109.37) ccw(c1391.98,3097.39) 1375.04,3097.39 1375.04,3076.3 ccw(c1403.92,3076.29) 1383.5,3055.87 1444.2,2995.16 cw(c1379.91,2930.88) 1470.83,2930.88 ; 1470.83,2930.87 1470.83,2910.37 ccw(c1516.3,2910.37) 1484.15,2878.22 1501,2861.37 cw(c1468.4,2828.77) 1514.5,2828.77 1514.5,2704.52 1516.23,2702.8 J4.76@1516.23,2677.37
  BOTTOM w5.3: v1(1137.7,3199.37) ccw(c1131.6,3205.47) 1140.23,3205.47 1140.23,3240.17 cw(c1163.42,3240.17) 1163.42,3263.37 1217.71,3263.37 cw(c1217.71,3245.77) 1230.15,3258.21 1254.45,3233.92 ccw(c1258.2,3237.67) 1258.2,3232.37 1329.13,3232.37 cw(c1329.13,3183.05) 1378.45,3183.05 1378.45,3113.12 ccw(c1383.75,3113.12) v1(1380,3109.37)
TYPEC0_SSTX1P/DP0_TX1P: C197.2 J4.74 | length 991.3
  TOP w5.3: v1(1163.7,3199.67) 1153.11,3210.26 cw(c1156.85,3214.01) 1151.55,3214.01 1151.55,3234.7 cw(c1157.98,3234.7) 1157.98,3241.12 ccw(c1157.98,3247.55) 1164.4,3247.55 1164.4,3255.9 ccw(c1157.98,3255.9) 1157.98,3262.32 cw(c1157.98,3268.75) 1151.55,3268.75 1151.55,3279.05 cw(c1156.85,3279.05) 1153.11,3282.8 C197.2@1170,3299.69 ; v1(1354,3109.37) cw(c1332.9,3088.27) 1362.74,3088.27 1362.74,3076.29 ccw(c1403.92,3076.29) 1374.8,3047.18 1435.51,2986.47 cw(c1379.91,2930.88) 1458.53,2930.88 1458.53,2910.37 ccw(c1516.3,2910.37) 1475.45,2869.52 1492.3,2852.67 cw(c1468.4,2828.77) 1502.2,2828.77 1502.2,2704.52 1500.48,2702.8 J4.74@1500.48,2677.37
  BOTTOM w5.3: v1(1163.7,3199.67) 1154.07,3209.35 cw(c1157.83,3213.09) 1152.53,3213.09 1152.53,3240.17 cw(c1163.42,3240.17) 1163.42,3251.07 1173.72,3251.07 1179.82,3244.97 1201.02,3244.97 1207.12,3251.07 1217.71,3251.07 cw(c1217.71,3245.77) 1221.46,3249.52 1245.75,3225.23 ccw(c1258.2,3237.67) 1258.2,3220.07 1329.13,3220.07 cw(c1329.13,3183.05) 1366.15,3183.05 1366.15,3129.37 cw(c1347.19,3129.37) 1360.59,3115.96 v1(1354,3109.37)
TYPEC0_SSTX2N/DP0_TX3N: C200.2 J4.66 | length 1043.3
  TOP w5.3: C200.2@940,3299.69 952.3,3287.39 cw(c948.55,3283.64) 953.85,3283.64 953.85,3242.52 cw(c930.46,3242.52) v1(947,3225.98) ; v1(1047.66,3106.22) ccw(c1064.19,3122.76) 1064.19,3099.37 1081.78,3099.37 cw(c1081.77,3043.3) 1121.42,3082.95 1126.63,3077.74 ccw(c1165.42,3116.53) 1165.42,3061.67 1208.57,3061.67 cw(c1208.57,2979.28) 1266.83,3037.54 1356.64,2947.73 cw(c1299.28,2890.37) 1380.4,2890.37 ccw(c1428.68,2890.37) 1394.54,2856.23 1403.8,2846.97 cw(c1326.63,2769.8) 1435.76,2769.8 1435.76,2704.52 1437.49,2702.8 J4.66@1437.49,2677.37
  BOTTOM w5.3: v1(947,3225.98) 952.3,3220.69 cw(c948.55,3216.94) 953.85,3216.94 953.85,3211.64 ccw(c973.42,3211.64) 973.42,3192.07 1044.34,3192.07 cw(c1044.34,3148.71) 1075,3179.37 1099.39,3154.98 cw(c1073.79,3129.37) 1110,3129.37 1110,3114.37 cw(c1095,3114.37) 1095,3099.37 1064.19,3099.37 cw(c1064.2,3122.76) v1(1047.66,3106.22)
TYPEC0_SSTX2P/DP0_TX3P: C199.2 J4.64 | length 1043.3
  TOP w5.3: v1(973,3225.98) cw(c989.54,3242.52) 966.15,3242.52 966.15,3283.64 cw(c971.45,3283.64) 967.7,3287.39 C199.2@980,3299.69 ; v1(1047.66,3080.22) cw(c1064.19,3063.68) 1064.19,3087.07 1081.78,3087.07 ; 1081.77,3087.07 cw(c1081.77,3043.3) 1112.73,3074.25 ; 1112.72,3074.25 1117.94,3069.04 ccw(c1165.42,3116.53) 1165.42,3049.37 1208.57,3049.37 cw(c1208.57,2979.28) 1258.13,3028.84 1347.94,2939.03 cw(c1299.28,2890.37) 1368.1,2890.37 ccw(c1428.68,2890.37) 1385.84,2847.53 1395.1,2838.27 cw(c1326.63,2769.8) 1423.46,2769.8 1423.46,2704.52 1421.74,2702.8 J4.64@1421.74,2677.37
  BOTTOM w5.3: v1(973,3225.98) 967.7,3220.69 ccw(c971.45,3216.94) 966.15,3216.94 966.15,3211.64 ccw(c973.42,3211.64) 973.42,3204.37 1044.34,3204.37 cw(c1044.34,3148.71) 1083.7,3188.07 1108.09,3163.67 cw(c1073.79,3129.37) 1122.3,3129.37 1122.3,3114.37 cw(c1095,3114.37) 1095,3087.07 1064.19,3087.07 ccw(c1064.2,3063.68) v1(1047.66,3080.22)
TYPEC0_USB20_OTG_ID: J4.90 R234.2 | length 509.4
  TOP w6: J4.90@1626.46,2677.37 1626.46,2621.77 1637.86,2610.37 1746,2610.37 1774,2638.37 1774,2755.37 v1(1765,2764.37)
  BOTTOM w6: R234.2@1705,2629.05 1705,2704.37 v1(1765,2764.37)
TYPEC_CC1: C210.1 J30.A5 U37.4 U37.7 U39.10 U39.11 | length 3032.7
  TOP w6: v1(1119.03,3465.8) 1126.77,3473.54 J30.A5@1126.77,3506.29
  ART03 w5.3: v1(750,2964.37) 761.45,2975.82 761.45,2988.22 773.95,3000.72 1683.35,3000.72 1802.7,3120.07 1802.7,3134.07 1797.4,3139.37 v1(1795,3139.37) ; 1320,3474.37 1320,3604.37 1335,3619.37 v1(1435,3619.37)
  ART03 w6: v1(1119.03,3465.8) 1120.7,3467.47 1120.7,3468.71 1136.36,3484.37 1210,3484.37 1235,3459.37 1305,3459.37 1320,3474.37
  BOTTOM w5.3: v1(750,2964.37) 750,2959.37 750,2664.37 770,2644.37 800,2644.37 809.68,2634.69 C210.1@809.68,2499.37 830,2479.05 U39.10@867.36,2479.05 885.47,2497.16 U39.11@885.47,2507.01 ; U37.7@1454.68,3512.15 1454.68,3491.06 1458.38,3487.37 1458.38,3474.37 1470.88,3461.86 1491.02,3461.86 1510.17,3481.02 1638.91,3481.02 1795,3324.93 v1(1795,3139.37)
  BOTTOM w6: v1(1435,3619.37) 1454.68,3599.69 U37.4@1454.68,3546.59 U37.7@1454.68,3512.15
TYPEC_CC2: C209.1 J30.B5 U37.5 U37.6 U39.1 U39.14 | length 3400
  TOP w6: v1(1015,3674.37) 1065,3674.37 1084.2,3655.17 1084.2,3620.44 1076,3612.24 1076,3596.5 1077.95,3594.55 J30.B5@1077.95,3559.05
  ART03 w5.3: v1(785,2964.37) 773.75,2975.62 773.75,2983.12 779.05,2988.42 1688.45,2988.42 1815,3114.97 v1(1815,3179.37)
  BOTTOM w5.3: v1(785,2964.37) 778.95,2964.37 762.3,2947.72 762.3,2669.47 772.39,2659.37 995,2659.37 1045.45,2608.92 1045.45,2520.14 C209.1@1025,2499.69 1004.37,2479.05 U39.1@962.64,2479.05 960.31,2479.05 944.53,2494.84 U39.14@944.53,2507.01 ; U37.6@1474.37,3512.15 1474.37,3491.06 1470.67,3487.37 1470.67,3479.47 1475.97,3474.16 1485.92,3474.16 1505.08,3493.32 1644.01,3493.32 1807.3,3330.03 1807.3,3187.07 v1(1815,3179.37)
  BOTTOM w6: v1(1015,3674.37) 1021.25,3680.62 1201.45,3680.62 1234.72,3647.35 1447.02,3647.35 1474.37,3620 U37.5@1474.37,3546.59 U37.6@1474.37,3512.15
UART0_RX_M0: J5.60 U9.9 | length 2638.9
  TOP w6: v1(1395,444.37) 2320,444.37 2360,484.37 2360,564.37 2396.85,601.22 J5.60@2396.85,722.26
  BOTTOM w6: v1(1395,444.37) 1330,509.37 1330,614.37 1360,644.37 1360,857 1297.83,919.17 1297.83,984.83 1240,1042.65 1240,1324.37 1330,1414.37 1330,1534.37 1390,1594.37 1390,1637.17 1402,1649.17 U9.9@1445.2,1649.17
UART0_TX_M0: J5.64 U9.10 | length 2939.1
  TOP w6: v1(1355.63,444.37) 1375.63,424.37 2350,424.37 2395.63,470 2431,470 2442,481 2442,512 2428.34,525.66 J5.64@2428.34,722.26
  BOTTOM w6: v1(1355.63,444.37) 1307,493 1307,621.37 1335,649.37 1335,848 1272.68,910.32 1272.68,981.69 1220,1034.37 1220,1329.37 1310,1419.37 1310,1539.37 1370,1599.37 1370,1689.37 1390,1709.37 1485,1709.37 1494.8,1699.57 U9.10@1494.8,1649.17
UART4_DIR: J6.72 R65.1 U10.2 U10.3 | length 2216
  TOP w6: J6.72@2491.33,2677.37 2491.33,2632.74 2503.33,2620.74 v1(2530.26,2620.74)
  BOTTOM w6: v1(2530.26,2620.74) 2535,2616 2535,1819.37 2605,1749.37 3534.68,1749.37 R65.1@3574.68,1709.37 3580,1704.05 U10.3@3580,1637.8 3580,1584.37 3570,1574.37 3540,1574.37 3530,1584.37 U10.2@3530,1637.8
UART4_RX_M2: J5.97 U10.1 | length 1586.4
  TOP w6: J5.97@2696.06,826.59 2696.06,965.43 2715,984.37 2843,984.37 2855,996.37 2855,1529.37 2975,1649.37 3440,1649.37 v1(3480,1689.37)
  BOTTOM w6: U10.1@3480,1637.8 v1(3480,1689.37)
